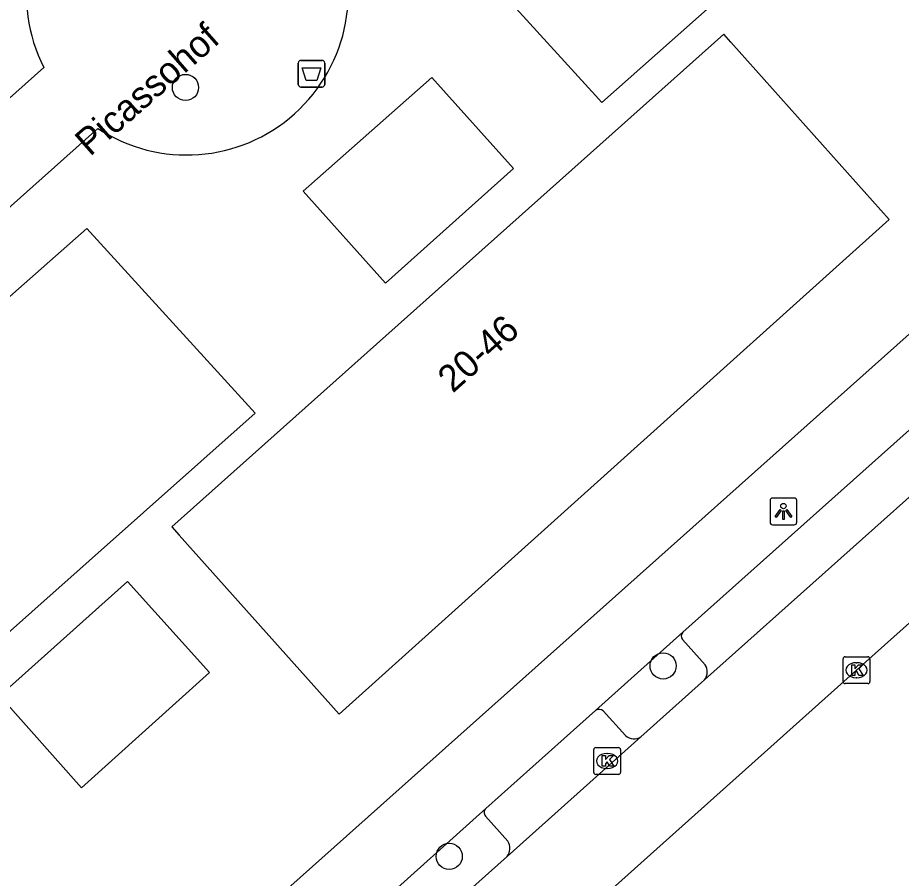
# Model space of a CAD drawing. Extents: x 162172 to 163187, y 382874 to 383684.
# Drawn here: x 162583.09 to 162616.09, y 383207.31 to 383239.45 of the extents above; entities that cross this region are included whole.
import ezdxf

# ---------------------------------------------------------------- set-up
doc = ezdxf.new("R2010")
doc.units = 0
for name, color, linetype in [('IMGEO_Afvalbak', 7, 'Continuous'), ('IMGEO_Boom', 7, 'Continuous'), ('IMGEO_Kolk', 7, 'Continuous'), ('IMGEO_Lichtpunt', 7, 'Continuous'), ('IMGEO_Openbare_ruimte_label', 7, 'Continuous'), ('IMGEO_Pand', 7, 'Continuous'), ('IMGEO_Pand_nummerreeks', 7, 'Continuous'), ('IMGEO_Rijbaan_lokaal_open', 7, 'Continuous'), ('IMGEO_Voetpad_open', 7, 'Continuous')]:
    doc.layers.add(name, color=color, linetype=linetype)

msp = doc.modelspace()

# ---------------------------------------------------------------- linework, layer by layer
at = {"layer": 'IMGEO_Afvalbak'}
for p, q in [((162593.57, 383236.96), (162593.57, 383237.76)), ((162593.57, 383237.76), (162593.57, 383236.96)), ((162593.67, 383237.86), (162594.46, 383237.86)), ((162594.46, 383237.86), (162593.67, 383237.86)), ((162594.56, 383237.76), (162594.56, 383236.96)), ((162594.56, 383236.96), (162594.56, 383237.76)), ((162594.46, 383236.86), (162593.67, 383236.86)), ((162593.67, 383236.86), (162594.46, 383236.86))]:
    msp.add_line(p, q, dxfattribs=at)
msp.add_lwpolyline([(162593.713, 383237.574), (162594.417, 383237.574), (162594.268, 383237.104), (162593.862, 383237.104), (162593.713, 383237.574)], dxfattribs=at)
for centre, start, end in [((162593.67, 383237.76), 90, 180), ((162593.67, 383237.76), 90, 180), ((162594.46, 383237.76), 0, 90), ((162594.46, 383237.76), 360, 90), ((162593.67, 383236.96), 180, 270), ((162593.67, 383236.96), 180, 270), ((162594.46, 383236.96), 270, 0), ((162594.46, 383236.96), 270, 0)]:
    msp.add_arc(centre, 0.1, start, end, dxfattribs=at)
at = {"layer": 'IMGEO_Boom'}
for centre in [(162589.359, 383236.848), (162607.195, 383215.244), (162599.207, 383208.131)]:
    msp.add_circle(centre, 0.489, dxfattribs=at)
at = {"layer": 'IMGEO_Kolk'}
for p, q in [((162613.991, 383215.584), (162614.843, 383215.584)), ((162613.916, 383214.658), (162613.916, 383215.51)), ((162614.404, 383215.364), (162614.429, 383215.364)), ((162614.917, 383215.51), (162614.917, 383214.658)), ((162614.427, 383214.804), (162614.402, 383214.804)), ((162614.843, 383214.584), (162613.991, 383214.584)), ((162604.604, 383211.268), (162604.604, 383212.12)), ((162604.679, 383212.194), (162605.531, 383212.194)), ((162605.092, 383211.974), (162605.117, 383211.974)), ((162605.605, 383212.12), (162605.605, 383211.268)), ((162605.115, 383211.414), (162605.09, 383211.414)), ((162605.531, 383211.194), (162604.679, 383211.194))]:
    msp.add_line(p, q, dxfattribs=at)
for points in [[(162613.991, 383215.584), (162614.843, 383215.584)], [(162613.916, 383214.658), (162613.916, 383215.51)], [(162614.237, 383215.284), (162614.36, 383215.284), (162614.36, 383215.133), (162614.49, 383215.284), (162614.654, 383215.284), (162614.508, 383215.133), (162614.661, 383214.884), (162614.509, 383214.884), (162614.424, 383215.048), (162614.36, 383214.981), (162614.36, 383214.884), (162614.237, 383214.884), (162614.237, 383215.284)], [(162614.917, 383215.51), (162614.917, 383214.658)], [(162614.843, 383214.584), (162613.991, 383214.584)], [(162604.604, 383211.268), (162604.604, 383212.12)], [(162604.679, 383212.194), (162605.531, 383212.194)], [(162605.605, 383212.12), (162605.605, 383211.268)], [(162604.925, 383211.894), (162605.048, 383211.894), (162605.048, 383211.743), (162605.178, 383211.894), (162605.342, 383211.894), (162605.196, 383211.743), (162605.349, 383211.494), (162605.197, 383211.494), (162605.112, 383211.658), (162605.048, 383211.591), (162605.048, 383211.494), (162604.925, 383211.494), (162604.925, 383211.894)], [(162605.531, 383211.194), (162604.679, 383211.194)]]:
    msp.add_lwpolyline(points, dxfattribs=at)
for centre, start, end in [((162613.993, 383215.508), 91.552, 178.448), ((162613.993, 383215.508), 91.552, 178.448), ((162614.841, 383215.508), 1.552, 88.448), ((162614.841, 383215.508), 1.552, 88.448), ((162613.993, 383214.66), 181.552, 268.448), ((162613.993, 383214.66), 181.552, 268.448), ((162614.841, 383214.66), 271.552, 358.448), ((162614.841, 383214.66), 271.552, 358.448), ((162604.681, 383212.118), 91.552, 178.448), ((162604.681, 383212.118), 91.552, 178.448), ((162605.529, 383212.118), 1.552, 88.448), ((162605.529, 383212.118), 1.552, 88.448), ((162604.681, 383211.27), 181.552, 268.448), ((162604.681, 383211.27), 181.552, 268.448), ((162605.529, 383211.27), 271.552, 358.448), ((162605.529, 383211.27), 271.552, 358.448)]:
    msp.add_arc(centre, 0.0765, start, end, dxfattribs=at)
for centre, major_axis, ratio, start_param, end_param in [((162614.403, 383215.084), (-0.387, 0.002), 0.722429, 4.712389, 7.853982), ((162614.428, 383215.084), (-0.39, 0.002), 0.717154, 1.570796, 4.712389), ((162605.091, 383211.694), (-0.387, 0.002), 0.722429, 4.712389, 7.853982), ((162605.116, 383211.694), (-0.39, 0.002), 0.717154, 1.570796, 4.712389)]:
    msp.add_ellipse(centre, major_axis=major_axis, ratio=ratio, start_param=start_param, end_param=end_param, dxfattribs=at)
at = {"layer": 'IMGEO_Lichtpunt'}
for p, q in [((162611.189, 383221.417), (162611.189, 383220.61)), ((162611.189, 383221.417), (162611.189, 383220.61)), ((162612.091, 383221.512), (162611.283, 383221.512)), ((162612.091, 383221.512), (162611.283, 383221.512)), ((162612.185, 383220.61), (162612.185, 383221.417)), ((162612.185, 383220.61), (162612.185, 383221.417)), ((162611.283, 383220.516), (162612.091, 383220.516)), ((162611.283, 383220.516), (162612.091, 383220.516))]:
    msp.add_line(p, q, dxfattribs=at)
for points in [[(162611.563, 383221.081), (162611.602, 383221.053), (162611.414, 383220.791), (162611.376, 383220.818), (162611.563, 383221.081)], [(162611.665, 383221.033), (162611.712, 383221.033), (162611.712, 383220.711), (162611.665, 383220.711), (162611.665, 383221.033)], [(162611.775, 383221.053), (162611.813, 383221.08), (162612, 383220.818), (162611.961, 383220.79), (162611.775, 383221.053)]]:
    msp.add_lwpolyline(points, dxfattribs=at)
msp.add_circle((162611.688, 383221.215), 0.0994, dxfattribs=at)
for centre, start, end in [((162611.283, 383221.417), 90, 180), ((162611.283, 383221.417), 90, 180), ((162612.091, 383221.417), 0, 90), ((162612.091, 383221.417), 0, 90), ((162611.283, 383220.61), 180, 270), ((162611.283, 383220.61), 180, 270), ((162612.091, 383220.61), 270, 0), ((162612.091, 383220.61), 270, 360)]:
    msp.add_arc(centre, 0.0946, start, end, dxfattribs=at)
at = {"layer": 'IMGEO_Pand'}
for points in [[(162618.517, 383248.913), (162617.541, 383250), (162612.456, 383255.66), (162606.162, 383250), (162598.611, 383243.209), (162604.667, 383236.552), (162604.912, 383236.283), (162618.793, 383248.606), (162618.517, 383248.913)], [(162609.726, 383238.535), (162609.459, 383238.834), (162588.848, 383220.443), (162589.127, 383220.13), (162595.098, 383213.44), (162615.634, 383231.921), (162609.726, 383238.535)], [(162596.828, 383229.54), (162601.612, 383233.816), (162598.559, 383237.213), (162593.753, 383232.971), (162596.828, 383229.54)], [(162591.966, 383224.686), (162591.716, 383224.96), (162585.677, 383231.574), (162571.72, 383219.265), (162578.021, 383212.3), (162581.578, 383215.46), (162591.966, 383224.686)], [(162582.413, 383214.123), (162585.48, 383210.692), (162590.257, 383214.996), (162587.192, 383218.399), (162582.413, 383214.123)]]:
    msp.add_lwpolyline(points, dxfattribs=at)
at = {"layer": 'IMGEO_Rijbaan_lokaal_open'}
for points in [[(162594.538, 383197.307), (162598.429, 383200.785), (162614.417, 383215.084), (162631.839, 383230.648), (162640.771, 383238.704), (162646.358, 383243.687), (162663.821, 383259.29), (162676.816, 383270.908), (162691.32, 383283.864), (162708.036, 383298.826), (162711.785, 383302.188)], [(162618.227, 383223.191), (162608.746, 383214.728)], [(162606.368, 383212.592), (162608.746, 383214.728)], [(162606.368, 383212.592), (162601.371, 383208.121)], [(162601.371, 383208.121), (162598.236, 383205.326)]]:
    msp.add_lwpolyline(points, dxfattribs=at)
at = {"layer": 'IMGEO_Voetpad_open'}
for points in [[(162645.781, 383253.871), (162641.443, 383250), (162588.21, 383202.497), (162586.39, 383200.872)], [(162584.072, 383237.596), (162566.646, 383222.046)], [(162568.622, 383219.741), (162586.091, 383235.314)], [(162607.933, 383216.501), (162616.51, 383224.164)], [(162604.674, 383213.579), (162607.933, 383216.501)], [(162608.768, 383215.286), (162607.92, 383216.227)], [(162600.573, 383209.92), (162604.674, 383213.579)], [(162604.956, 383213.564), (162605.789, 383212.64)], [(162596.549, 383206.31), (162600.573, 383209.92)], [(162601.392, 383208.699), (162600.56, 383209.634)]]:
    msp.add_lwpolyline(points, dxfattribs=at)
for centre, radius, start, end in [((162589.422, 383240.337), 6.011, 56.4721, 207.1288), ((162589.403, 383240.362), 6.037, 236.7307, 26.9751), ((162608.075, 383216.357), 0.202, 134.556, 220.0112), ((162608.349, 383215.023), 0.495, 323.3649, 32.1195), ((162604.806, 383213.393), 0.228, 48.6186, 125.2919), ((162606.114, 383213.042), 0.517, 231.0928, 299.4291), ((162600.709, 383209.771), 0.202, 132.261, 222.5339), ((162600.956, 383208.425), 0.515, 323.7617, 32.0768)]:
    msp.add_arc(centre, radius, start, end, dxfattribs=at)

# ---------------------------------------------------------------- texts
at = {"layer": 'IMGEO_Openbare_ruimte_label'}
msp.add_text('Picassohof', height=1, rotation=41.3099, dxfattribs=at).set_placement((162585.792, 383234.245))
at = {"layer": 'IMGEO_Pand_nummerreeks'}
msp.add_text('20-46', height=1, rotation=41.7422, dxfattribs=at).set_placement((162599.34, 383225.409))

doc.saveas('drawing.dxf')
